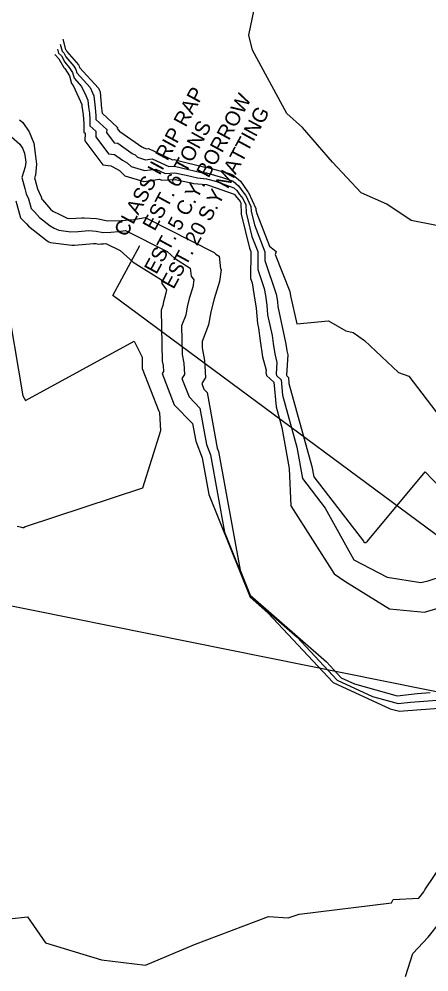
# Model space of a CAD drawing. Extents: x 1368651 to 1378602, y 762048 to 779328.
# Drawn here: x 1377080.7 to 1377164.1, y 762965.4 to 763159.3 of the extents above; entities that cross this region are included whole.
import ezdxf

# ---------------------------------------------------------------- set-up
doc = ezdxf.new("R2010")
doc.units = 0
for name, color, linetype in [('DTM Contours Major', 7, 'Continuous'), ('DTM Contours Minor', 7, 'Continuous'), ('Prop Erosion Rip Rap Class I Label', 7, 'Continuous')]:
    doc.layers.add(name, color=color, linetype=linetype)

msp = doc.modelspace()

# ---------------------------------------------------------------- linework, layer by layer
at = {"layer": 'DTM Contours Major'}
for points in [[(1377088.52, 763153.14), (1377088.73, 763152.32), (1377089.3, 763151.77), (1377090, 763150.49), (1377090.91, 763149.43), (1377091.59, 763148.35), (1377091.9, 763147.23), (1377093.41, 763145.56), (1377094.26, 763143.72), (1377094.69, 763142.72), (1377094.82, 763141.36), (1377095, 763140.08), (1377095.09, 763138.82), (1377095.11, 763137.56), (1377096.33, 763136.41), (1377096.28, 763135.3), (1377098.88, 763131.85), (1377100.07, 763131.7), (1377101.74, 763130.53), (1377102.71, 763130.01), (1377103.48, 763129.27), (1377106.23, 763128.41), (1377108.54, 763128.74), (1377110.43, 763127.84), (1377112.39, 763127.98), (1377114.7, 763127.47), (1377116.96, 763126.92), (1377118.81, 763126.75), (1377120.66, 763126.24), (1377124.35, 763124.93), (1377124.96, 763124.4), (1377125.56, 763123.56), (1377126.22, 763122.74), (1377126.82, 763121.46), (1377126.88, 763119.85), (1377128.07, 763115.01), (1377129.28, 763111.93), (1377129.25, 763108.31), (1377130.55, 763104.45), (1377130.8, 763102.98), (1377131.07, 763101.07), (1377131.26, 763099.05), (1377132.15, 763094.89), (1377132.39, 763093.22), (1377132.69, 763091.12), (1377133.14, 763089.4), (1377133, 763087.07), (1377133.07, 763086.72), (1377134.02, 763085.87), (1377134.28, 763082.75), (1377137.2, 763072.18), (1377138.34, 763065.75), (1377142.99, 763059.72), (1377148.79, 763049.23), (1377155.59, 763045.69), (1377162.44, 763044.59), (1377163.93, 763044.98), (1377167.03, 763045.98)], [(1377079.15, 763135.3), (1377080.84, 763133.77), (1377081.41, 763132.97), (1377081.81, 763131.98), (1377081.92, 763131.08), (1377082.03, 763130.15), (1377081.95, 763129.17), (1377081.26, 763126.99), (1377081.84, 763124.81), (1377082.12, 763123.7), (1377082.59, 763122.68), (1377083.15, 763120.7), (1377083.83, 763120.05), (1377084.84, 763118.86), (1377087, 763117.15), (1377087.84, 763116.73), (1377088.76, 763116.27), (1377091.23, 763115.97), (1377092.72, 763116.03), (1377094.87, 763116.22), (1377096.37, 763116.12), (1377097.77, 763115.85), (1377099.39, 763115.87), (1377100.94, 763116.02), (1377102.35, 763116.25), (1377110.81, 763111.93), (1377112.28, 763110.62), (1377115.53, 763108.58), (1377115.7, 763106.95), (1377116.23, 763106.23), (1377116.02, 763104.69), (1377115.3, 763102.39), (1377114.91, 763100.72), (1377114.59, 763099), (1377113.75, 763096.85), (1377113.88, 763091), (1377114.21, 763089.27), (1377114.35, 763086.93), (1377113.81, 763086.11), (1377115.27, 763082.37), (1377117.46, 763080.12), (1377118.81, 763072.67), (1377119.6, 763070.62), (1377122.47, 763054.84), (1377127.69, 763041.84), (1377137.25, 763033.47), (1377145.4, 763024.74), (1377152.57, 763021.45), (1377157.83, 763019.99), (1377160.29, 763020.26), (1377169.31, 763020.95)]]:
    msp.add_lwpolyline(points, dxfattribs=at)
at = {"layer": 'DTM Contours Minor'}
for points in [[(1377165.6, 763117.25), (1377160.43, 763118.26), (1377155.49, 763121.6), (1377150.3, 763123.91), (1377144.45, 763130.14), (1377138.38, 763137.17), (1377135.17, 763140.05), (1377128.2, 763152.89), (1377127.43, 763155.99), (1377131.75, 763176.95)], [(1377089.06, 763154.15), (1377089.44, 763152.69), (1377089.78, 763152.35), (1377090.21, 763151.57), (1377091.83, 763149.69), (1377092.25, 763149.02), (1377092.45, 763148.32), (1377095.13, 763145.36), (1377095.65, 763144.21), (1377095.92, 763143.6), (1377096.15, 763141.18), (1377096.27, 763140.39), (1377096.32, 763139.62), (1377096.33, 763138.84), (1377098.51, 763136.81), (1377098.47, 763136.14), (1377100.04, 763134.07), (1377100.75, 763133.99), (1377103.72, 763131.91), (1377104.3, 763131.6), (1377104.76, 763131.15), (1377106.4, 763130.64), (1377107.79, 763130.84), (1377111.15, 763129.23), (1377112.33, 763129.32), (1377113.72, 763129.01), (1377117.73, 763128.03), (1377118.82, 763127.94), (1377122.1, 763127.02), (1377124.26, 763126.25), (1377125.34, 763125.32), (1377126.4, 763123.83), (1377126.79, 763123.35), (1377127.84, 763121.09), (1377127.88, 763120.16), (1377128.57, 763117.36), (1377130.71, 763111.89), (1377130.7, 763110.13), (1377133, 763103.28), (1377133.12, 763102.61), (1377133.24, 763101.73), (1377133.33, 763100.8), (1377134.9, 763093.42), (1377135.01, 763092.67), (1377135.15, 763091.73), (1377135.35, 763090.96), (1377135.1, 763086.82), (1377135.13, 763086.68), (1377135.5, 763086.35), (1377135.6, 763085.12), (1377140.28, 763068.21), (1377140.65, 763066.12), (1377150.73, 763053.04), (1377150.84, 763052.84), (1377150.97, 763052.77), (1377151.13, 763052.74), (1377151.24, 763052.78), (1377151.6, 763053.05), (1377163.33, 763067.14), (1377166.46, 763063.88)], [(1377089.6, 763155.16), (1377090.14, 763153.06), (1377090.27, 763152.93), (1377090.43, 763152.65), (1377092.75, 763149.94), (1377092.92, 763149.68), (1377092.99, 763149.42), (1377096.85, 763145.16), (1377097.05, 763144.71), (1377097.16, 763144.47), (1377097.49, 763140.99), (1377097.53, 763140.7), (1377097.55, 763140.42), (1377097.56, 763140.13), (1377100.68, 763137.2), (1377100.67, 763136.98), (1377101.19, 763136.3), (1377101.42, 763136.27), (1377105.69, 763133.29), (1377105.89, 763133.18), (1377106.04, 763133.04), (1377106.58, 763132.87), (1377107.04, 763132.93), (1377111.87, 763130.62), (1377112.27, 763130.65), (1377112.74, 763130.55), (1377118.49, 763129.15), (1377118.82, 763129.12), (1377123.53, 763127.81), (1377124.17, 763127.58), (1377125.72, 763126.24), (1377127.24, 763124.1), (1377127.35, 763123.96), (1377128.87, 763120.71), (1377128.88, 763120.46), (1377129.06, 763119.71), (1377131.66, 763113.07), (1377133, 763111.96), (1377132.77, 763111.34), (1377135.77, 763103.82), (1377135.93, 763102.93), (1377137.22, 763097.22), (1377143.65, 763097.86), (1377147.2, 763095.82), (1377148.66, 763095.5), (1377150.94, 763093.83), (1377157.91, 763087.37), (1377160, 763086.57), (1377166.39, 763078.23)], [(1377087.98, 763152.14), (1377088.02, 763151.95), (1377088.81, 763151.18), (1377089.79, 763149.41), (1377089.99, 763149.18), (1377090.93, 763147.69), (1377091.36, 763146.14), (1377091.7, 763145.76), (1377092.86, 763143.22), (1377093.46, 763141.85), (1377093.48, 763141.55), (1377093.74, 763139.77), (1377093.85, 763138.02), (1377093.88, 763136.27), (1377094.16, 763136.01), (1377094.08, 763134.46), (1377097.73, 763129.62), (1377099.39, 763129.42), (1377099.77, 763129.16), (1377101.13, 763128.43), (1377102.21, 763127.38), (1377106.05, 763126.18), (1377109.29, 763126.65), (1377109.71, 763126.45), (1377112.45, 763126.64), (1377115.69, 763125.93), (1377116.19, 763125.81), (1377118.81, 763125.57), (1377119.22, 763125.46), (1377124.45, 763123.6), (1377124.58, 763123.48), (1377124.72, 763123.29), (1377125.66, 763122.12), (1377125.79, 763121.84), (1377125.88, 763119.55), (1377127.58, 763112.66), (1377127.85, 763111.98), (1377127.8, 763106.48), (1377128.09, 763105.62), (1377128.48, 763103.35), (1377128.9, 763100.4), (1377129.19, 763097.29), (1377129.39, 763096.36), (1377129.76, 763093.77), (1377130.24, 763090.52), (1377130.94, 763087.84), (1377130.9, 763087.32), (1377131.02, 763086.75), (1377132.54, 763085.39), (1377132.96, 763080.37), (1377134.13, 763076.14), (1377135.61, 763067.8), (1377135.98, 763060.24), (1377144.81, 763046.41), (1377146.93, 763044.86), (1377156.07, 763039.25), (1377163.16, 763038.61), (1377174.36, 763041.89)], [(1377080.8, 763138.78), (1377081.04, 763138.55), (1377081.42, 763138.21), (1377082.74, 763136.34), (1377083.68, 763134.02), (1377083.94, 763131.91), (1377084.2, 763129.74), (1377084.01, 763127.46), (1377083.85, 763126.97), (1377083.99, 763126.48), (1377084.43, 763124.7), (1377085.19, 763123.07), (1377085.31, 763122.62), (1377085.46, 763122.48), (1377087.09, 763120.58), (1377087.57, 763120.2), (1377088.96, 763119.5), (1377090.47, 763118.76), (1377091.02, 763118.69), (1377093.47, 763118.79), (1377093.95, 763118.83), (1377096.44, 763118.67), (1377098.75, 763118.22), (1377101.44, 763118.26), (1377104.01, 763118.5), (1377106.34, 763118.89), (1377120.36, 763111.73), (1377120.69, 763111.44), (1377121.41, 763110.98), (1377121.68, 763108.45), (1377121.8, 763108.28), (1377121.47, 763105.89), (1377120.35, 763102.3), (1377119.73, 763099.7), (1377119.23, 763097.01), (1377117.92, 763093.67), (1377117.95, 763092.36), (1377118.44, 763089.79), (1377118.64, 763086.3), (1377117.84, 763085.08), (1377118.28, 763083.95), (1377118.94, 763083.27), (1377120.98, 763071.98), (1377121.24, 763071.29), (1377125.64, 763047.15), (1377127.69, 763042.04), (1377143.2, 763028.46), (1377146.24, 763025.2), (1377148.92, 763023.98), (1377157.6, 763021.57), (1377161.65, 763022.01), (1377164.3, 763022.21)], [(1377080, 763122.29), (1377080.98, 763118.78), (1377082.19, 763117.61), (1377082.6, 763117.14), (1377086.42, 763114.1), (1377086.72, 763113.95), (1377087.05, 763113.79), (1377091.45, 763113.25), (1377091.98, 763113.27), (1377095.8, 763113.6), (1377096.31, 763113.57), (1377096.79, 763113.48), (1377097.35, 763113.49), (1377097.88, 763113.54), (1377098.36, 763113.62), (1377101.25, 763112.14), (1377103.88, 763109.81), (1377109.64, 763106.18), (1377109.72, 763105.46), (1377110.67, 763104.17), (1377110.58, 763103.49), (1377110.26, 763102.48), (1377110.08, 763101.74), (1377109.94, 763100.98), (1377109.57, 763100.04), (1377109.82, 763089.64), (1377109.99, 763088.76), (1377110.06, 763087.56), (1377109.78, 763087.15), (1377112.27, 763080.78), (1377115.99, 763076.97), (1377116.63, 763073.37), (1377117.95, 763069.95), (1377119.3, 763062.54), (1377127.68, 763041.64), (1377131.29, 763038.48), (1377144.56, 763024.28), (1377156.22, 763018.92), (1377158.07, 763018.41), (1377158.93, 763018.5), (1377174.32, 763019.69)], [(1377078.02, 763103.08), (1377081.43, 763082.57), (1377082.02, 763081.65), (1377104.11, 763093.7), (1377105.7, 763090.46), (1377105.75, 763088.28), (1377105.76, 763088.24), (1377105.76, 763088.2), (1377105.75, 763088.18), (1377109.14, 763079.49), (1377109.23, 763079.2), (1377109.46, 763075.49), (1377105.81, 763063.78), (1377081.94, 763055.95), (1377081.65, 763055.72), (1377081.43, 763055.75), (1377081.24, 763055.8), (1377080.31, 763056.04)], [(1377078.69, 762976.2), (1377082.37, 762976.57), (1377086.06, 762971.33), (1377097.47, 762967.86), (1377106.43, 762966.76), (1377116.37, 762971), (1377131.43, 762976.7), (1377135.46, 762976.42), (1377137.69, 762977.13), (1377156.47, 762979.42), (1377156.78, 762980.1), (1377162.04, 762980.38), (1377163.06, 762981.69), (1377163.23, 762982.08), (1377167.2, 762987.92)], [(1377159.31, 762964.48), (1377160.81, 762969.17), (1377163.93, 762972.49), (1377166.26, 762975.46)]]:
    msp.add_lwpolyline(points, dxfattribs=at)
at = {"layer": 'Prop Erosion Rip Rap Class I Label'}
for points in [[(1377184.06, 763040.65), (1377099.77, 763103.04), (1377105.23, 763113.17)], [(1377170.95, 763021.3), (1377019.59, 763051.83), (1377023.75, 763059.33)]]:
    msp.add_lwpolyline(points, dxfattribs=at)

# ---------------------------------------------------------------- texts
for s, p in [('CLASS II RIP RAP', (1377102.49, 763114.74)), ('EST. 5 C.Y. BORROW', (1377108.62, 763107.15)), ('EST. 20 S.Y MATTING', (1377112.11, 763104.14)), ('EST. 6 TONS', (1377108.27, 763115.96))]:
    msp.add_text(s, height=3, rotation=61.5756, dxfattribs=at).set_placement(p)

doc.saveas('drawing.dxf')
